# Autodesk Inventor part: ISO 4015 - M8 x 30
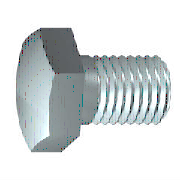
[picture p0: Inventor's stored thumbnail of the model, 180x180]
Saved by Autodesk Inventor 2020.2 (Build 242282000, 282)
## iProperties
IsCustomPart: 0
Manager: www.cadconsulting.pl
Company: Fabian Stasiak CAD Consulting
Created: 2013-02
Part Number: ISO 4015 - M8 x 30
Material: Stal nierdzewna 440C
Description: Śruby z łbem sześciokątnym. Z redukowaną częścią trzonu. Klasa produkcyjna B
Document SubType Name: Modeling
Standard: ISO 4015
Designer: F.Stasiak
Standard Revision: First edition 1979-07-01
Standards Organization: ISO
Language: pl-PL
Size Designation: M8 x 30
Categories: <MemberInstance><Categories><Category DisplayName="Mocowania" InternalName="e4da775c-781d-43d5-af7c-5136215cf5a6" Mnemonic="FSTN"><Category DisplayName="Śruby"
Density: 7.75 g/cm^3
Appearance: Częściowo polerowana
Author: F.Stasiak
Subject: Zbiór ćwiczeń. Autodesk Inventor 2020. Kurs podstawowy
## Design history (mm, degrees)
sketch "Sketch5"
  geometry: C1 r 4.875 at (0, 0); A1 r 6.5 centre (0, 0) between (5.629, 3.25) and (0, 6.5) reference
  constraints: 1 centre point, 1 coincident
  dimensions: "d27" = 9.75 diameter of C1 (= 0.75 x ParS)
extrude "Extrusion2" cut sketch "Sketch5" distance "d28" = 1.06 (= 0.2 x ParK); taper "d29" = 0 deg
node "MSC_A1"
node "MSC_PF1"
node "MSC_PT1"
fillet "Fillet1" dims "d30" = 0.4 (= r)
body "Solid1"
revolve "Obrót1" stored, may be unused: angle "d8" = 90 deg
sketch "Szkic3"
  geometry: L1 (0, 6.5)-(3.753, 6.5); L2 (3.753, 6.5)-(7.506, 0); L3 (7.506, 0)-(0, 0); L4 (0, 0)-(0, 6.5); L5 (-3.753, 6.5)-(-7.506, 0); L6 (0, 6.5)-(-3.753, 6.5); L7 (-3.753, -6.5)-(-7.506, 0); L8 (0, -6.5)-(-3.753, -6.5); L9 (0, -6.5)-(3.753, -6.5); L10 (3.753, -6.5)-(7.506, 0); C1 r 3.55 at (0, 0) reference
  constraints: 20 end point, 5 symmetric about line, 1 horizontal, 1 parallel, 1 perpendicular, 6 other
  dimensions: "d9" = 60 deg angle of L3 L2; "ParS" = 13 distance of L9.end L1.end; "msp_d11" = 13 distance between parallel lines of L10 L5 (= ParS)
extrude "Wyciągnięcie proste1" join sketch "Szkic3" taper "d13" = 0 deg; distance "ParK" = 5.3
revolve "Obrót2" stored, may be unused: angle "d16" = 90 deg
feature "Gwint1" dims "d18" = 0, "msp_d17" = 22 (= b)
sketch "Szkic2"
  geometry: L1 (0, -6.578)-(0, -36.578); L2 (0, -36.578)-(3.375, -36.578); L3 (4, -35.953)-(4, -14.578); L4 (4, -14.578)-(3.55, -13.799); L5 (3.55, -13.799)-(3.55, -6.578); L6 (3.55, -6.578)-(0, -6.578); L7 (3.375, -36.578)-(4, -35.953); L8 (4, -36.578)-(4, -37.462); L9 (0, -43.639)-(0, -0.401) reference; 1 further point
  constraints: 16 end point, 3 parallel, 2 collinear, 2 perpendicular, 2 point on line, 1 equal length, 1 horizontal alignment, 1 vertical
  dimensions: "Ds" = 7.1 diameter of L5 L1; "NND" = 8 diameter of L3 L1; "b" = 22 distance of point (4, -36.578) L3.end; "d3" = 30 deg angle of L3 L4; "d5" = 45 deg angle of L2 L7; "PTC" = 1.25 diameter of L2.end L8; "NLG" = 30 distance of L1.start L1.end
sketch "Szkic4"
  geometry: L1 (-6.5, -1.278)-(-7.506, -1.278); L2 (-7.506, -1.278)-(-7.506, -1.859); L3 (-7.506, -1.859)-(-6.5, -1.278); L4 (0, -13.445)-(0, 34.627) reference; L5 (0, 27.759)-(0, 27.179); L6 (-7.506, -6.578)-(-7.506, -1.278) reference; L7 (-3.753, -1.278)-(-7.506, -1.278) reference
  constraints: 8 end point, 4 collinear, 1 horizontal, 1 parallel, 1 perpendicular
  dimensions: "d14" = 30 deg angle of L3 L1; "msp_d15" = 13 diameter of L1.start L5 (= ParS)
other parameters: "d22" = 0, "d23" = 0, "d25" = 0, "d26" = 0, "r" = 0.4 [user parameter; used in 1 equation term], "d31" = 0, "THREADDIA" = 8 (= NND) [user parameter]
